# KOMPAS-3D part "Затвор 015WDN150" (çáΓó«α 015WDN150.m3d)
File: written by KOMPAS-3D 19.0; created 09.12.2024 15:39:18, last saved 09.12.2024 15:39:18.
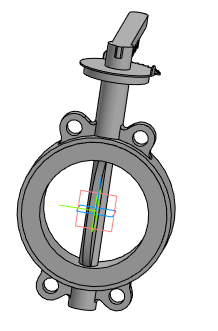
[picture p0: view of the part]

Document properties: Автор: Евгений; Полное имя файла: ..\Затвор 015WDN150.a3d

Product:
- Part/product: Затвор 015WDN150
    Масса: 20.0218

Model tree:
1. Операция без истории:1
